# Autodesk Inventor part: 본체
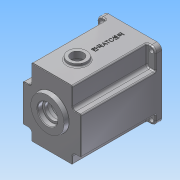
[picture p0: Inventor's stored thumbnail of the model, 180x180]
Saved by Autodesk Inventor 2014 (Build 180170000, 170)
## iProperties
Created: 2016-02
Part Number: 본체
Material: 알루미늄 6061
Document SubType Name: Modeling
Designer: mduedu
Density: 2.71 g/cm^3
Mass: 1343.57 g
Surface Area: 1127.09 cm^2
Volume: 495.782 cm^3
Appearance: 알루미늄 - 평지
Author: mduedu
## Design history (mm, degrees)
sketch "스케치1"
  geometry: L1 (-47, -47)-(47, -47); L2 (47, -47)-(47, 63); L3 (47, 63)-(-47, 63); L4 (-47, 63)-(-47, -47); 2 further points
  constraints: 8 end point, 2 parallel, 1 horizontal, 1 midpoint, 1 perpendicular, 1 vertical alignment
  dimensions: "d0" = 94 distance of L2.end L3.end; "d155" = 110 distance of L1.end L2.end; "d156" = 47 distance from line of L1 point (0, 0)
extrude "돌출1" new body sketch "스케치1" distance "d2" = 130; taper "d3" = 0 deg
sketch "스케치3"
  geometry: C1 r 40 at (0, 0); 1 further point
  constraints: 1 centre point, 1 coincident
  dimensions: "d9" = 80 diameter of C1
extrude "돌출3" cut sketch "스케치3" distance "d11" = 121; taper "d12" = 0 deg
sketch "스케치4"
  geometry: C1 r 21 at (0, 11); 1 further point
  constraints: 1 centre point, 1 vertical alignment
  dimensions: "d13" = 21 radius of C1; "d15" = 11 distance of point (0, 0) C1.centre
extrude "돌출4" join sketch "스케치4" distance "d16" = 7; taper "d17" = 0 deg
sketch "스케치5"
  geometry: C1 r 15 at (0, -20); 1 further point
  constraints: 1 centre point, 1 vertical alignment
  dimensions: "d18" = 15 radius of C1; "d20" = 20 distance of point (0, 0) C1.centre
extrude "돌출5" join sketch "스케치5" distance "d21" = 7; taper "d22" = 0 deg
sketch "스케치6"
  geometry: C1 r 28 at (0, 11); A1 r 21 centre (0, 11) between (8.978, -7.984) and (-8.978, -7.984) reference; 1 further point
  constraints: 1 centre point, 1 coincident
  dimensions: "d23" = 56 diameter of C1
extrude "돌출6" join sketch "스케치6" distance "d25" = 7; taper "d26" = -10 deg
hole "구멍1" diameter "d29" = 35; stored, may be unused: countersink angle "d33" = 90 deg, drill point angle "d35" = 0 deg; dims "d27" = 10, "d28" = 10, "d30" = 6, "d31" = 4, "d32" = 2, "d34" = 10
hole "구멍2" diameter "d38" = 22; stored, may be unused: countersink angle "d42" = 90 deg, drill point angle "d44" = 0 deg; dims "d36" = 10, "d37" = 10, "d39" = 6, "d40" = 4, "d41" = 2, "d43" = 7
hole "구멍3" diameter "d47" = 19; stored, may be unused: countersink angle "d51" = 90 deg, drill point angle "d53" = 0 deg; dims "d45" = 10, "d46" = 10, "d48" = 6, "d49" = 4, "d50" = 2, "d52" = 1
hole "구멍4" diameter "d56" = 32; stored, may be unused: countersink angle "d60" = 90 deg, drill point angle "d62" = 0 deg; dims "d54" = 10, "d55" = 10, "d57" = 6, "d58" = 4, "d59" = 2, "d61" = 8
hole "구멍5" diameter "d65" = 25; stored, may be unused: countersink angle "d69" = 90 deg, drill point angle "d71" = 0 deg; dims "d63" = 10, "d64" = 10, "d66" = 6, "d67" = 4, "d68" = 2, "d70" = 8
fillet "모깎기2" dims "d73" = 0.3
fillet "모깎기3" dims "d74" = 2
chamfer "모따기1" distance "d75" = 1; stored, may be unused: second distance "d76" = 2, angle "d77" = 45 deg
fillet "모깎기4" dims "d78" = 3
sketch "스케치16"
  geometry: L1 (-23, 32.726)-(23, 32.726); L2 (23, 32.726)-(23, 53); L3 (23, 53)-(-23, 53); L4 (-23, 53)-(-23, 32.726); L5 (-47, 63)-(47, 63) reference; 3 further points
  constraints: 8 end point, 2 parallel, 1 horizontal, 1 midpoint, 1 perpendicular, 1 vertical alignment, 2 other
  dimensions: "d160" = 46 distance of L2.end L3.end; "d163" = 10 distance between parallel lines of L3 L5
extrude "돌출15" cut sketch "스케치16" stored distance "d164" = 10; taper "d165" = 0 deg
fillet "모깎기5" dims "d79" = 2
fillet "모깎기15" dims "d166" = 5
sketch "스케치7"
  geometry: L1 (-23, 48)-(-23, 35.228) reference; L2 (23, 35.228)-(23, 48) reference; L3 (18, 53)-(-18, 53) reference; L4 (47, 63)-(47, -47) reference; L5 (47, -47)-(-47, -47) reference; L6 (-47, -47)-(-47, 63) reference; L7 (-47, 63)-(47, 63) reference; L8 (-26, 48)-(-26, 35.228); L9 (26, 35.228)-(26, 48); L10 (18, 56)-(-18, 56); C1 r 43 at (0, 0); A1 r 5 centre (-18, 48) between (-18, 53) and (-23, 48) reference; A2 r 5 centre (-28, 35.228) between (-24.889, 31.314) and (-23, 35.228) reference; A3 r 40 centre (0, 0) between (-24.889, 31.314) and (24.889, 31.314) reference; A4 r 5 centre (28, 35.228) between (23, 35.228) and (24.889, 31.314) reference; A5 r 5 centre (18, 48) between (23, 48) and (18, 53) reference; A6 r 8 centre (-18, 48) between (-18, 56) and (-26, 48); A7 r 2 centre (-28, 35.228) between (-26.756, 33.662) and (-26, 35.228); A8 r 43 centre (0, 0) between (-26.756, 33.662) and (26.756, 33.662); A9 r 2 centre (28, 35.228) between (26, 35.228) and (26.756, 33.662); A10 r 8 centre (18, 48) between (26, 48) and (18, 56); 1 further point
  constraints: 10 point on circle, 6 centre point, 6 end point, 1 coincident, 7 other
  dimensions: "d80" = 86 diameter of C1; "d167" = 3 distance between parallel lines of L3 L10
extrude "돌출7" cut sketch "스케치7" distance "d83" = 9; taper "d84" = 0 deg
sketch "스케치8" dims "d168" = 36
  geometry: L1 (-36, 4)-(-39.799, 4); L2 (-36, -4)-(-39.799, -4); A1 r 4 centre (-36, 0) between (-36, 4) and (-36, -4); A2 r 40 centre (0, 0) between (-24.889, 31.314) and (24.889, 31.314) reference; A3 r 40 centre (0, 0) between (-39.799, 4) and (-39.799, -4); 2 further points
  constraints: 5 point on circle, 4 end point, 2 centre point, 2 coincident, 2 horizontal alignment, 2 tangent, 1 horizontal, 1 parallel, 2 other
  dimensions: "d169" = 4 radius of A1
extrude "돌출9" join sketch "스케치8" stored distance "d89" = 9; taper "d90" = 0 deg
fillet "모깎기6" dims "d91" = 3.5
sketch "스케치9"
  geometry: L1 (47, 63)-(-47, 63) reference; L2 (47, -47)-(47, 63) reference; L3 (47, 63)-(33, 63); L4 (33, 63)-(33, 30); L5 (33, 30)-(47, 30); L6 (47, 30)-(47, 63); 2 further points
  constraints: 8 end point, 2 parallel, 1 horizontal, 1 perpendicular
  dimensions: "d95" = 33 distance from line of L4 point (0, 0); "d96" = 30 distance from line of L5 point (0, 0)
extrude "돌출10" cut sketch "스케치9" distance "d97" = 120; taper "d98" = 0 deg
sketch "스케치11"
  geometry: L1 (-40, -40)-(40, -40); L2 (40, -40)-(40, 56); L3 (40, 56)-(-40, 56); L4 (-40, 56)-(-40, -40); L5 (-47, -47)-(47, -47) reference; L6 (47, 63)-(-47, 63) reference; L7 (-47, 63)-(-47, -47) reference; C1 r 3.5 at (-40, 56); C2 r 3.5 at (40, 56); C3 r 3.5 at (40, -40); C4 r 3.5 at (-40, -40); 1 further point
  constraints: 8 end point, 4 centre point, 4 coincident, 3 equal radius, 2 parallel, 1 horizontal, 1 perpendicular
  dimensions: "d109" = 80 distance of L2.end L3.end; "d112" = 7 diameter of C1; "d157" = 7 distance from line of L1.start L5; "d158" = 7 distance between parallel lines of L6 L3; "d159" = 7 distance from line of L7 L3.end
extrude "돌출12" cut sketch "스케치11" stored distance "d113" = 63; taper "d114" = 0 deg
fillet "모깎기7" dims "d115" = 8
fillet "모깎기8" dims "d116" = 5
fillet "모깎기11" dims "d119" = 2
fillet "모깎기12" dims "d120" = 2
fillet "모깎기13" dims "d121" = 2
sketch "스케치12"
  geometry: 3 further points
  constraints: 2 horizontal alignment
hole "구멍6" sketch "스케치12" at (36, 0), (-36, 0) diameter "d122" = 3.242; stored, may be unused: countersink angle "d126" = 90 deg, drill point angle "d128" = 120 deg; dims "d123" = 7, "d124" = 4, "d125" = 2, "d127" = 9
sketch "스케치13"
  geometry: L1 (-33, 35)-(-33, 61) reference; L2 (-31, 63)-(31, 63) reference; L3 (33, 61)-(33, 35) reference; L4 (33, -35)-(33, -45) reference; L5 (31, -47)-(-31, -47) reference; L6 (-33, -45)-(-33, -35) reference; L7 (38, 30)-(45, 30) reference; L8 (47, 28)-(47, -28) reference; L9 (45, -30)-(38, -30) reference; L10 (-38, -30)-(-45, -30) reference; L11 (-47, -28)-(-47, 28) reference; L12 (-45, 30)-(-38, 30) reference; L13 (31, 62)-(-31, 62); L14 (-32, 61)-(-32, 35); L15 (-38, 29)-(-45, 29); L16 (-46, 28)-(-46, -28); L17 (-45, -29)-(-38, -29); L18 (-32, -35)-(-32, -45); L19 (-31, -46)-(31, -46); L20 (32, -45)-(32, -35); L21 (38, -29)-(45, -29); L22 (46, -28)-(46, 28); L23 (45, 29)-(38, 29); L24 (32, 35)-(32, 61); L25 (38, 30)-(45, 30) reference; L26 (47, 28)-(47, -28) reference; L27 (45, -30)-(38, -30) reference; L28 (33, -35)-(33, -45) reference; L29 (31, -47)-(-31, -47) reference; L30 (-33, -45)-(-33, -35) reference; L31 (-38, -30)-(-45, -30) reference; L32 (-47, -28)-(-47, 28) reference; L33 (-45, 30)-(-38, 30) reference; L34 (-33, 35)-(-33, 61) reference; L35 (33, 61)-(33, 35) reference; L36 (-31, 63)-(31, 63) reference; C1 r 16 at (0, 11) reference; C2 r 28 at (0, 11) reference; C3 r 16 at (0, 11) reference; C4 r 28 at (0, 11) reference; A1 r 5 centre (-38, 35) between (-38, 30) and (-33, 35) reference; A2 r 2 centre (-31, 61) between (-31, 63) and (-33, 61) reference; A3 r 2 centre (31, 61) between (33, 61) and (31, 63) reference; A4 r 5 centre (38, 35) between (33, 35) and (38, 30) reference; A5 r 5 centre (38, -35) between (38, -30) and (33, -35) reference; A6 r 2 centre (31, -45) between (31, -47) and (33, -45) reference; A7 r 2 centre (-31, -45) between (-33, -45) and (-31, -47) reference; A8 r 5 centre (-38, -35) between (-33, -35) and (-38, -30) reference; A9 r 2 centre (45, 28) between (47, 28) and (45, 30) reference; A10 r 2 centre (45, -28) between (45, -30) and (47, -28) reference; A11 r 2 centre (-45, -28) between (-47, -28) and (-45, -30) reference; A12 r 2 centre (-45, 28) between (-45, 30) and (-47, 28) reference; A13 r 1 centre (-31, 61) between (-31, 62) and (-32, 61); A14 r 6 centre (-38, 35) between (-38, 29) and (-32, 35); A15 r 1 centre (-45, 28) between (-45, 29) and (-46, 28); A16 r 1 centre (-45, -28) between (-46, -28) and (-45, -29); A17 r 6 centre (-38, -35) between (-32, -35) and (-38, -29); A18 r 1 centre (-31, -45) between (-32, -45) and (-31, -46); A19 r 1 centre (31, -45) between (31, -46) and (32, -45); A20 r 6 centre (38, -35) between (38, -29) and (32, -35); A21 r 1 centre (45, -28) between (45, -29) and (46, -28); A22 r 1 centre (45, 28) between (46, 28) and (45, 29); A23 r 6 centre (38, 35) between (32, 35) and (38, 29); A24 r 1 centre (31, 61) between (32, 61) and (31, 62); A25 r 5 centre (38, 35) between (33, 35) and (38, 30) reference; A26 r 2 centre (45, 28) between (47, 28) and (45, 30) reference; A27 r 2 centre (45, -28) between (45, -30) and (47, -28) reference; A28 r 5 centre (38, -35) between (38, -30) and (33, -35) reference; A29 r 2 centre (31, -45) between (31, -47) and (33, -45) reference; A30 r 2 centre (-31, -45) between (-33, -45) and (-31, -47) reference; A31 r 5 centre (-38, -35) between (-33, -35) and (-38, -30) reference; A32 r 2 centre (-45, -28) between (-47, -28) and (-45, -30) reference; A33 r 2 centre (-45, 28) between (-45, 30) and (-47, 28) reference; A34 r 5 centre (-38, 35) between (-38, 30) and (-33, 35) reference; A35 r 2 centre (-31, 61) between (-31, 63) and (-33, 61) reference; A36 r 2 centre (31, 61) between (33, 61) and (31, 63) reference
  constraints: 24 end point, 24 point on circle, 12 centre point, 23 other
  dimensions: "d154" = 1 distance between parallel lines of L13 L2
extrude "돌출13" cut sketch "스케치13" distance "d130" = 1; taper "d131" = 0 deg
fillet "모깎기14" dims "d147" = 0.3
sketch "스케치15"
  geometry: L1 (78, 0)-(0, 0) reference; 3 further points
  constraints: 1 midpoint, 1 vertical alignment, 1 other
  dimensions: "d148" = 40 distance of point (39, -40) point (39, 0)
feature "엠보싱1" sketch "스케치15" dims "d22" = 0, "d149" = 0.5, "d150" = 0
chamfer "모따기4" distance "d151" = 1; stored, may be unused: second distance "d152" = 2, angle "d153" = 45 deg
sketch "스케치17"
  geometry: L1 (39.004, -17.213)-(39.004, -18.809) reference; L2 (39.004, -18.809)-(38.548, -18.809) reference; L3 (38.548, -18.809)-(38.548, -17.213) reference; L4 (38.548, -17.213)-(35.455, -17.213) reference; L5 (35.455, -17.213)-(35.455, -16.822) reference; L6 (35.772, -16.659)-(42.578, -16.659) reference; L7 (42.578, -16.659)-(42.578, -17.213) reference; L8 (42.578, -17.213)-(39.004, -17.213) reference; L9 (38.223, -56.73)-(38.695, -56.73) reference; L10 (38.695, -56.73)-(38.695, -58.073) reference; L11 (38.695, -58.073)-(40.787, -58.073) reference; L12 (40.787, -58.073)-(40.787, -58.643) reference; L13 (40.787, -58.643)-(35.398, -58.643) reference; L14 (35.398, -58.643)-(35.398, -58.277) reference; L15 (35.715, -58.073)-(38.223, -58.073) reference; L16 (38.223, -58.073)-(38.223, -56.73) reference; L17 (41.927, -57.813)-(42.383, -57.813) reference; L18 (42.383, -57.813)-(42.383, -63.031) reference; L19 (42.383, -63.031)-(40.429, -63.031) reference; L20 (40.429, -63.031)-(40.429, -62.608) reference; L21 (40.689, -62.478)-(41.927, -62.478) reference; L22 (41.927, -62.478)-(41.927, -57.813) reference; L23 (36.09, -60.849)-(36.09, -62.624) reference; L24 (36.09, -62.624)-(35.666, -62.624) reference; L25 (35.666, -62.624)-(35.666, -60.849) reference; L26 (35.666, -60.849)-(36.09, -60.849) reference; L27 (37.058, -64.057)-(36.635, -64.057) reference; L28 (36.635, -64.057)-(36.635, -59.539) reference; L29 (36.635, -59.539)-(37.058, -59.539) reference; L30 (37.058, -59.539)-(37.058, -64.057) reference; L31 (42.138, -43.501)-(40.307, -44.168) reference; L32 (40.307, -44.168)-(40.307, -46.871) reference; L33 (40.307, -46.871)-(42.138, -47.555) reference; L34 (42.138, -47.555)-(42.138, -48.133) reference; L35 (42.138, -48.133)-(36.138, -45.853) reference; L36 (36.138, -45.853)-(36.138, -45.202) reference; L37 (36.138, -45.202)-(42.138, -42.923) reference; L38 (42.138, -42.923)-(42.138, -43.501) reference; L39 (36.725, -45.536)-(39.81, -46.684) reference; L40 (39.81, -46.684)-(39.81, -44.364) reference; L41 (39.81, -44.364)-(36.725, -45.536) reference; L42 (40.022, -52.114)-(40.022, -49.94) reference; L43 (40.022, -49.94)-(42.57, -49.94) reference; L44 (42.57, -49.94)-(42.57, -50.494) reference; L45 (42.57, -50.494)-(40.469, -50.494) reference; L46 (40.469, -50.494)-(40.469, -55.094) reference; L47 (40.469, -55.094)-(40.022, -55.094) reference; L48 (40.022, -55.094)-(40.022, -52.659) reference; L49 (40.022, -52.659)-(38.556, -52.659) reference; L50 (38.556, -52.659)-(38.556, -55.973) reference; L51 (38.556, -55.973)-(38.109, -55.973) reference; L52 (38.109, -55.973)-(38.109, -50.73) reference; L53 (36.106, -50.388)-(36.106, -54.955) reference; L54 (36.106, -54.955)-(35.65, -54.955) reference; L55 (35.65, -54.955)-(35.65, -49.81) reference; L56 (38.109, -50.136)-(38.109, -48.768) reference; L57 (38.109, -48.768)-(38.556, -48.768) reference; L58 (38.556, -48.768)-(38.556, -52.114) reference; L59 (38.556, -52.114)-(40.022, -52.114) reference; L60 (36.138, -38.168)-(36.635, -38.168) reference; L61 (36.635, -38.168)-(36.635, -40.041) reference; L62 (36.635, -40.041)-(42.138, -40.041) reference; L63 (42.138, -40.041)-(42.138, -40.586) reference; L64 (42.138, -40.586)-(36.635, -40.586) reference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; C1 r 10 at (39, -89); A1 r 4 centre (4, -12) between (8, -12) and (4, -8) reference; A2 r 4 centre (74, -12) between (74, -8) and (70, -12) reference; 61 further points
  constraints: 2 end point, 1 centre point, 1 midpoint, 1 point on line, 76 other
  dimensions: "d170" = 20 diameter of C1; "d171" = 41 distance from line of C1.centre L110
extrude "돌출16" cut sketch "스케치17" stored distance "d172" = 10; taper "d173" = 0 deg
sketch "스케치18"
  geometry: C1 r 10 at (39, -89) reference; C2 r 15 at (39, -89); 1 further point
  constraints: 1 centre point, 1 coincident
  dimensions: "d174" = 30 diameter of C2
extrude "돌출17" join sketch "스케치18" distance "d175" = 5; taper "d176" = 0 deg
fillet "모깎기16" dims "d177" = 2
sketch "스케치19"
  geometry: C1 r 10 at (18, 80) reference; C2 r 15 at (18, 80); 1 further point
  constraints: 1 centre point, 1 coincident
  dimensions: "d178" = 30 diameter of C2
extrude "돌출18" cut sketch "스케치19" distance "d181" = 5; taper "d182" = 0 deg
chamfer "모따기5" distance "d183" = 0.5; stored, may be unused: second distance "d184" = 2, angle "d185" = 45 deg
node "솔리드1"
pattern_circular "원형 패턴1" dims angle "d93" = 360 deg
mirror "대칭1"
mirror "대칭2"
node "절단 모서리 투영1"
node "절단 모서리 투영2"
node "절단 모서리 투영3"
node "절단 모서리 투영4"
